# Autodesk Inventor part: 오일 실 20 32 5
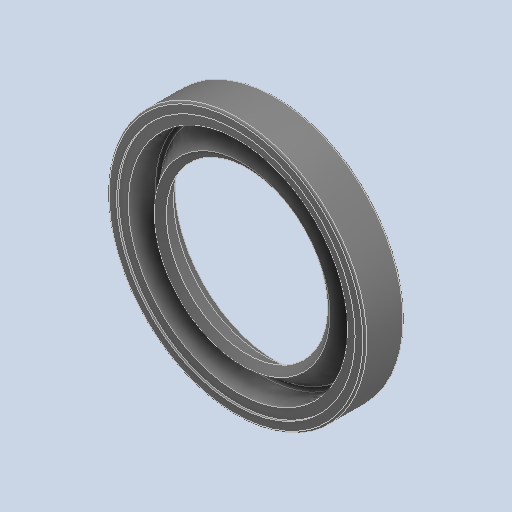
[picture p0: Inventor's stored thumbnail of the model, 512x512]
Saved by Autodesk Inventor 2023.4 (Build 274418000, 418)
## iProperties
Created: 2024-04
Part Number: 오일 실 20 32 5
Material: 고무
Description: 오일 실 - 비스프링, 조립 GA
Document SubType Name: Modeling
Designer: EDU
Density: 0.93 g/cm^3
Appearance: 기본값
Author: jhkim
Sending System: Autodesk Inventor 2025
Preprocessor: ST-DEVELOPER v20
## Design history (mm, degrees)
node "오일 실 20 32 51"
node "솔리드1"
body "Solid1"
